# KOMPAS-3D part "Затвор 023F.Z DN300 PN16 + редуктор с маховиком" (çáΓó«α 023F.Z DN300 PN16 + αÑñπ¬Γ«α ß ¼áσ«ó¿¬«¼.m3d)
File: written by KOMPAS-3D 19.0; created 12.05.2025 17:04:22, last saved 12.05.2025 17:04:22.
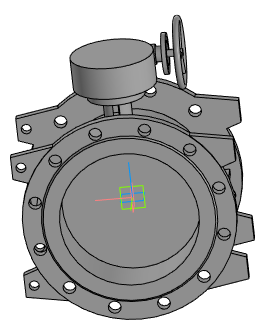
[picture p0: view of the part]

Document properties: Полное имя файла: Затвор 023F.Z DN300 PN16 + редуктор с маховиком.a3d

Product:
- Part/product: Затвор 023F.Z DN300 PN16 + редуктор с маховиком
    Масса: 101.018

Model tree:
1. Операция без истории:1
